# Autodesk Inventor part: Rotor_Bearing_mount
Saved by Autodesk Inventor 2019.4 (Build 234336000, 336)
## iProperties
Created: 2020-02
Part Number: Rotor_Bearing_mount
Material: Generic
Document SubType Name: Modeling
Designer: Administrator
Density: 1 g/cm^3
Appearance: Default
Title: Rotor_Bearing_mount v5
Author: Administrator
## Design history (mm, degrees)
feature "Body3"
body "Solid1"
